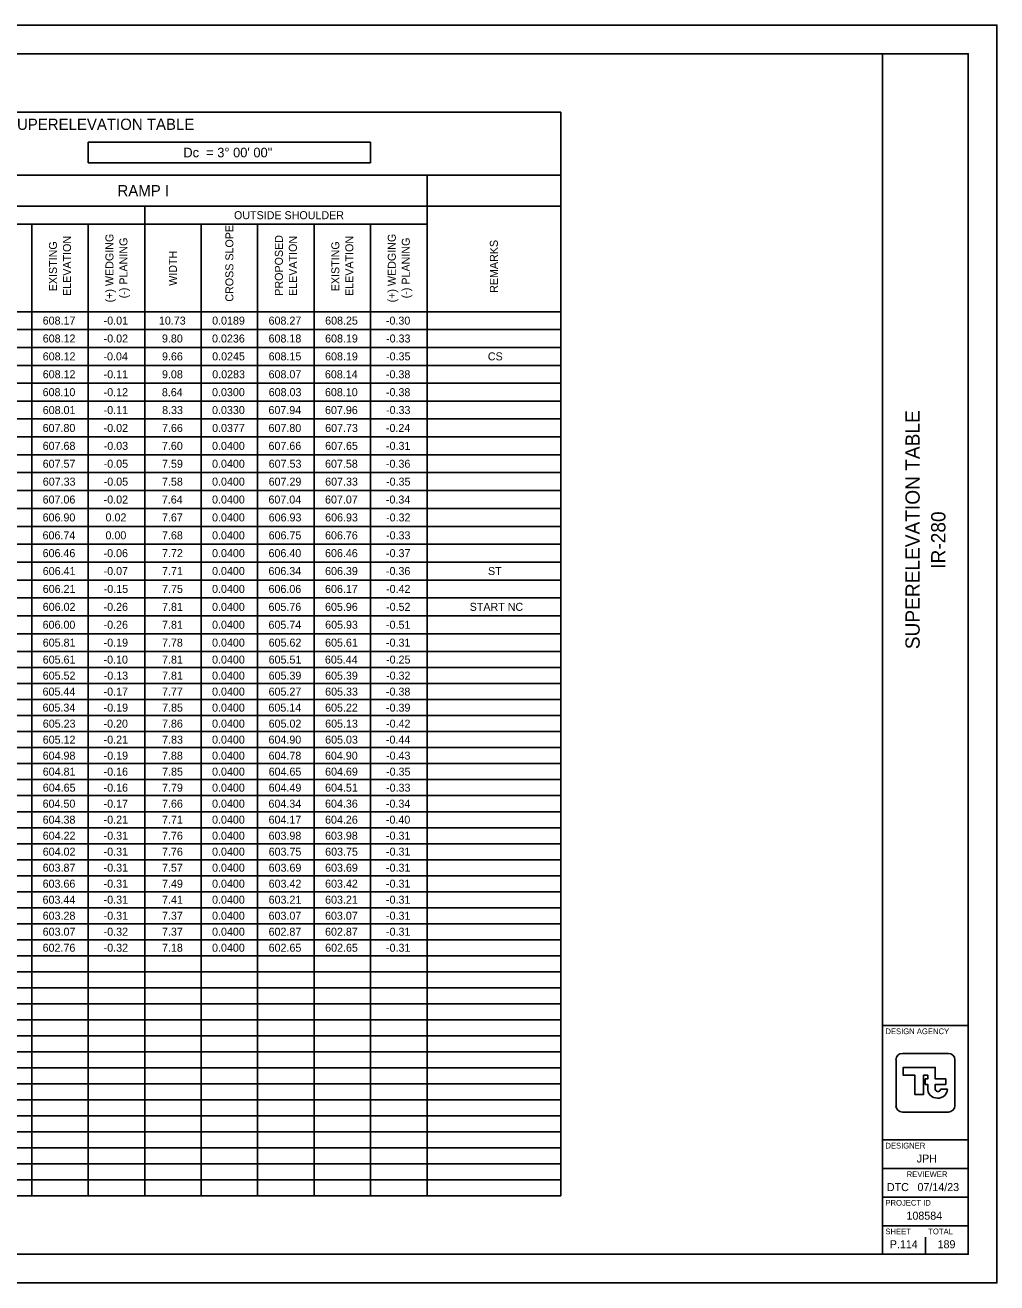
# Model space of a CAD drawing. Extents: x 0 to 34, y 0 to 22.
# Drawn here: x 17 to 34, y 0 to 22 of the extents above; entities that cross this region are included whole.
import ezdxf

# ---------------------------------------------------------------- set-up
doc = ezdxf.new("R2010")
doc.units = 0
for name, color, linetype in [('Default', 7, 'Continuous'), ('SH_Border', 7, 'Continuous'), ('SH_Cut_Line', 7, 'Continuous'), ('SH_Data', 7, 'Continuous')]:
    doc.layers.add(name, color=color, linetype=linetype)

msp = doc.modelspace()

# ---------------------------------------------------------------- linework, layer by layer
at = {"layer": 'Default'}
for p, q in [((7.13, 20.48), (26.368, 20.48)), ((26.368, 20.48), (26.368, 1.522)), ((18.099, 19.953), (23.041, 19.953)), ((18.099, 19.953), (18.099, 19.591)), ((23.041, 19.953), (23.041, 19.591)), ((18.099, 19.591), (23.041, 19.591)), ((7.13, 19.376), (26.368, 19.376)), ((24.029, 19.376), (24.029, 1.522)), ((7.13, 18.833), (26.368, 18.833)), ((19.088, 18.833), (19.088, 1.522)), ((9.205, 18.52), (24.029, 18.52)), ((17.111, 18.52), (17.111, 1.522)), ((18.099, 18.52), (18.099, 1.522)), ((20.076, 18.52), (20.076, 1.522)), ((21.064, 18.52), (21.064, 1.522)), ((22.052, 18.52), (22.052, 1.522)), ((23.041, 18.52), (23.041, 1.522)), ((7.13, 16.988), (26.368, 16.988)), ((7.13, 16.675), (26.368, 16.675)), ((7.13, 16.362), (26.368, 16.362)), ((7.13, 16.049), (26.368, 16.049)), ((7.13, 15.736), (26.368, 15.736)), ((7.13, 15.424), (26.368, 15.424)), ((7.13, 15.111), (26.368, 15.111)), ((7.13, 14.798), (26.368, 14.798)), ((7.13, 14.485), (26.368, 14.485)), ((7.13, 14.172), (26.368, 14.172)), ((7.13, 13.859), (26.368, 13.859)), ((7.13, 13.546), (26.368, 13.546)), ((7.13, 13.233), (26.368, 13.233)), ((7.13, 12.92), (26.368, 12.92)), ((7.13, 12.607), (26.368, 12.607)), ((7.13, 12.294), (26.368, 12.294)), ((7.13, 11.981), (26.368, 11.981)), ((7.13, 11.668), (26.368, 11.668)), ((7.13, 11.355), (26.368, 11.355)), ((7.13, 11.042), (26.368, 11.042)), ((7.13, 10.762), (26.368, 10.762)), ((7.13, 10.482), (26.368, 10.482)), ((7.13, 10.202), (26.368, 10.202)), ((7.13, 9.922), (26.368, 9.922)), ((7.13, 9.642), (26.368, 9.642)), ((7.13, 9.362), (26.368, 9.362)), ((7.13, 9.082), (26.368, 9.082)), ((7.13, 8.802), (26.368, 8.802)), ((7.13, 8.522), (26.368, 8.522)), ((7.13, 8.242), (26.368, 8.242)), ((7.13, 7.962), (26.368, 7.962)), ((7.13, 7.682), (26.368, 7.682)), ((7.13, 7.402), (26.368, 7.402)), ((7.13, 7.122), (26.368, 7.122)), ((7.13, 6.842), (26.368, 6.842)), ((7.13, 6.562), (26.368, 6.562)), ((7.13, 6.282), (26.368, 6.282)), ((7.13, 6.002), (26.368, 6.002)), ((7.13, 5.722), (26.368, 5.722)), ((7.13, 5.442), (26.368, 5.442)), ((7.13, 5.162), (26.368, 5.162)), ((7.13, 4.882), (26.368, 4.882)), ((7.13, 4.602), (26.368, 4.602)), ((7.13, 4.322), (26.368, 4.322)), ((7.13, 4.042), (26.368, 4.042)), ((7.13, 3.762), (26.368, 3.762)), ((7.13, 3.482), (26.368, 3.482)), ((7.13, 3.202), (26.368, 3.202)), ((7.13, 2.922), (26.368, 2.922)), ((7.13, 2.642), (26.368, 2.642)), ((7.13, 2.362), (26.368, 2.362)), ((7.13, 2.082), (26.368, 2.082)), ((7.13, 1.802), (26.368, 1.802)), ((7.13, 1.522), (26.368, 1.522))]:
    msp.add_line(p, q, dxfattribs=at)
at = {"layer": 'SH_Border'}
for p, q in [((32, 0.5), (32, 21.5)), ((32, 4.5), (33.5, 4.5)), ((32, 2.5), (33.5, 2.5)), ((32, 2), (33.5, 2)), ((32, 1.5), (33.5, 1.5)), ((32, 1), (33.5, 1))]:
    msp.add_line(p, q, dxfattribs=at)
msp.add_lwpolyline([(1.5, 21.5), (33.5, 21.5), (33.5, 0.5), (1.5, 0.5)], close=True, dxfattribs=at)
at = {"layer": 'SH_Cut_Line'}
msp.add_lwpolyline([(0, 0), (34, 0), (34, 22), (0, 22)], close=True, dxfattribs=at)
at = {"layer": 'SH_Data'}
for p, q in [((32.75, 3.5), (32.75, 3.5)), ((32.791, 3.415), (32.791, 3.415)), ((33.136, 3.385), (33.015, 3.385)), ((32.375, 0.675), (32.375, 0.675)), ((32.75, 0.5), (32.75, 0.8))]:
    msp.add_line(p, q, dxfattribs=at)
for points in [[(32.348, 4.014), (33.152, 4.014)], [(32.236, 3.099), (32.236, 3.901)], [(32.922, 3.399), (32.922, 3.47), (33.107, 3.47), (33.107, 3.568), (32.922, 3.568), (32.922, 3.768), (32.361, 3.768), (32.361, 3.632), (32.566, 3.632), (32.566, 3.294), (32.715, 3.294), (32.715, 3.63), (32.79, 3.63), (32.79, 3.568), (32.748, 3.568), (32.748, 3.47), (32.79, 3.47), (32.79, 3.415), (32.791, 3.415)], [(33.264, 3.901), (33.264, 3.099)], [(33.152, 2.986), (32.348, 2.986)]]:
    msp.add_lwpolyline(points, dxfattribs=at)
for centre, radius, start, end in [((32.348, 3.901), 0.113, 90, 180), ((33.152, 3.901), 0.113, 360, 90), ((32.949, 3.392), 0.16, 171.8856, 274.8323), ((32.968, 3.392), 0.0473, 171.8856, 350.9243), ((32.976, 3.392), 0.16, 265.1677, 357.3201), ((32.348, 3.099), 0.113, 180, 270), ((33.152, 3.099), 0.113, 270, 360)]:
    msp.add_arc(centre, radius, start, end, dxfattribs=at)

# ---------------------------------------------------------------- texts
at = {"layer": 'Default'}
for s, height, p in [('WOO/LUC-280-06.20/00.00 - SUPERELEVATION TABLE', 0.196, (13.197, 20.168)), ('Dc  = 3° 00\' 00"', 0.168, (19.765, 19.688)), ('RAMP I', 0.196, (18.612, 19.007)), ('OUTSIDE SHOULDER', 0.14, (20.651, 18.606)), ('608.17', 0.14, (17.303, 16.762)), ('-0.01', 0.14, (18.37, 16.762)), ('10.73', 0.14, (19.337, 16.762)), ('0.0189', 0.14, (20.268, 16.762)), ('608.27', 0.14, (21.256, 16.762)), ('608.25', 0.14, (22.246, 16.762)), ('-0.30', 0.14, (23.309, 16.762)), ('608.12', 0.14, (17.304, 16.449)), ('-0.02', 0.14, (18.37, 16.449)), ('9.80', 0.14, (19.39, 16.449)), ('0.0236', 0.14, (20.267, 16.449)), ('608.18', 0.14, (21.256, 16.449)), ('608.19', 0.14, (22.245, 16.449)), ('-0.33', 0.14, (23.312, 16.449)), ('608.12', 0.14, (17.304, 16.136)), ('-0.04', 0.14, (18.367, 16.136)), ('9.66', 0.14, (19.391, 16.136)), ('0.0245', 0.14, (20.269, 16.136)), ('608.15', 0.14, (21.257, 16.136)), ('608.19', 0.14, (22.245, 16.136)), ('-0.35', 0.14, (23.312, 16.136)), ('CS', 0.14, (25.093, 16.136)), ('608.12', 0.14, (17.304, 15.823)), ('-0.11', 0.14, (18.37, 15.823)), ('9.08', 0.14, (19.391, 15.823)), ('0.0283', 0.14, (20.27, 15.823)), ('608.07', 0.14, (21.256, 15.823)), ('608.14', 0.14, (22.242, 15.823)), ('-0.38', 0.14, (23.31, 15.823)), ('608.10', 0.14, (17.302, 15.51)), ('-0.12', 0.14, (18.37, 15.51)), ('8.64', 0.14, (19.389, 15.51)), ('0.0300', 0.14, (20.267, 15.51)), ('608.03', 0.14, (21.258, 15.51)), ('608.10', 0.14, (22.243, 15.51)), ('-0.38', 0.14, (23.31, 15.51)), ('608.01', 0.14, (17.304, 15.197)), ('-0.11', 0.14, (18.37, 15.197)), ('8.33', 0.14, (19.393, 15.197)), ('0.0330', 0.14, (20.267, 15.197)), ('607.94', 0.14, (21.254, 15.197)), ('607.96', 0.14, (22.244, 15.197)), ('-0.33', 0.14, (23.312, 15.197)), ('607.80', 0.14, (17.302, 14.884)), ('-0.02', 0.14, (18.37, 14.884)), ('7.66', 0.14, (19.391, 14.884)), ('0.0377', 0.14, (20.268, 14.884)), ('607.80', 0.14, (21.255, 14.884)), ('607.73', 0.14, (22.246, 14.884)), ('-0.24', 0.14, (23.309, 14.884)), ('607.68', 0.14, (17.303, 14.571)), ('-0.03', 0.14, (18.371, 14.571)), ('7.60', 0.14, (19.39, 14.571)), ('0.0400', 0.14, (20.267, 14.571)), ('607.66', 0.14, (21.255, 14.571)), ('607.65', 0.14, (22.246, 14.571)), ('-0.31', 0.14, (23.311, 14.571)), ('607.57', 0.14, (17.303, 14.258)), ('-0.05', 0.14, (18.371, 14.258)), ('7.59', 0.14, (19.392, 14.258)), ('0.0400', 0.14, (20.267, 14.258)), ('607.53', 0.14, (21.258, 14.258)), ('607.58', 0.14, (22.244, 14.258)), ('-0.36', 0.14, (23.31, 14.258)), ('607.33', 0.14, (17.305, 13.945)), ('-0.05', 0.14, (18.371, 13.945)), ('7.58', 0.14, (19.391, 13.945)), ('0.0400', 0.14, (20.267, 13.945)), ('607.29', 0.14, (21.257, 13.945)), ('607.33', 0.14, (22.246, 13.945)), ('-0.35', 0.14, (23.312, 13.945)), ('607.06', 0.14, (17.302, 13.632)), ('-0.02', 0.14, (18.37, 13.632)), ('7.64', 0.14, (19.389, 13.632)), ('0.0400', 0.14, (20.267, 13.632)), ('607.04', 0.14, (21.254, 13.632)), ('607.07', 0.14, (22.244, 13.632)), ('-0.34', 0.14, (23.309, 13.632)), ('606.90', 0.14, (17.302, 13.319)), ('0.02', 0.14, (18.404, 13.319)), ('7.67', 0.14, (19.391, 13.319)), ('0.0400', 0.14, (20.267, 13.319)), ('606.93', 0.14, (21.258, 13.319)), ('606.93', 0.14, (22.246, 13.319)), ('-0.32', 0.14, (23.312, 13.319)), ('606.74', 0.14, (17.301, 13.006)), ('0.00', 0.14, (18.402, 13.006)), ('7.68', 0.14, (19.391, 13.006)), ('0.0400', 0.14, (20.267, 13.006)), ('606.75', 0.14, (21.257, 13.006)), ('606.76', 0.14, (22.244, 13.006)), ('-0.33', 0.14, (23.312, 13.006)), ('606.46', 0.14, (17.302, 12.694)), ('-0.06', 0.14, (18.369, 12.694)), ('7.72', 0.14, (19.392, 12.694)), ('0.0400', 0.14, (20.267, 12.694)), ('606.40', 0.14, (21.255, 12.694)), ('606.46', 0.14, (22.244, 12.694)), ('-0.37', 0.14, (23.311, 12.694)), ('606.41', 0.14, (17.304, 12.381)), ('-0.07', 0.14, (18.369, 12.381)), ('7.71', 0.14, (19.392, 12.381)), ('0.0400', 0.14, (20.267, 12.381)), ('606.34', 0.14, (21.254, 12.381)), ('606.39', 0.14, (22.245, 12.381)), ('-0.36', 0.14, (23.31, 12.381)), ('ST', 0.14, (25.095, 12.381)), ('606.21', 0.14, (17.304, 12.068)), ('-0.15', 0.14, (18.371, 12.068)), ('7.75', 0.14, (19.393, 12.068)), ('0.0400', 0.14, (20.267, 12.068)), ('606.06', 0.14, (21.255, 12.068)), ('606.17', 0.14, (22.244, 12.068)), ('-0.42', 0.14, (23.312, 12.068)), ('606.02', 0.14, (17.304, 11.755)), ('-0.26', 0.14, (18.369, 11.755)), ('7.81', 0.14, (19.392, 11.755)), ('0.0400', 0.14, (20.267, 11.755)), ('605.76', 0.14, (21.255, 11.755)), ('605.96', 0.14, (22.244, 11.755)), ('-0.52', 0.14, (23.312, 11.755)), ('START NC', 0.14, (24.775, 11.755)), ('606.00', 0.14, (17.302, 11.442)), ('-0.26', 0.14, (18.369, 11.442)), ('7.81', 0.14, (19.392, 11.442)), ('0.0400', 0.14, (20.267, 11.442)), ('605.74', 0.14, (21.254, 11.442)), ('605.93', 0.14, (22.246, 11.442)), ('-0.51', 0.14, (23.311, 11.442)), ('605.81', 0.14, (17.304, 11.129)), ('-0.19', 0.14, (18.37, 11.129)), ('7.78', 0.14, (19.391, 11.129)), ('0.0400', 0.14, (20.267, 11.129)), ('605.62', 0.14, (21.257, 11.129)), ('605.61', 0.14, (22.245, 11.129)), ('-0.31', 0.14, (23.311, 11.129)), ('605.61', 0.14, (17.304, 10.832)), ('-0.10', 0.14, (18.368, 10.832)), ('7.81', 0.14, (19.392, 10.832)), ('0.0400', 0.14, (20.267, 10.832)), ('605.51', 0.14, (21.257, 10.832)), ('605.44', 0.14, (22.242, 10.832)), ('-0.25', 0.14, (23.312, 10.832)), ('605.52', 0.14, (17.304, 10.552)), ('-0.13', 0.14, (18.371, 10.552)), ('7.81', 0.14, (19.392, 10.552)), ('0.0400', 0.14, (20.267, 10.552)), ('605.39', 0.14, (21.257, 10.552)), ('605.39', 0.14, (22.245, 10.552)), ('-0.32', 0.14, (23.312, 10.552)), ('605.44', 0.14, (17.301, 10.272)), ('-0.17', 0.14, (18.369, 10.272)), ('7.77', 0.14, (19.391, 10.272)), ('0.0400', 0.14, (20.267, 10.272)), ('605.27', 0.14, (21.256, 10.272)), ('605.33', 0.14, (22.246, 10.272)), ('-0.38', 0.14, (23.31, 10.272)), ('605.34', 0.14, (17.301, 9.992)), ('-0.19', 0.14, (18.37, 9.992)), ('7.85', 0.14, (19.393, 9.992)), ('0.0400', 0.14, (20.267, 9.992)), ('605.14', 0.14, (21.254, 9.992)), ('605.22', 0.14, (22.245, 9.992)), ('-0.39', 0.14, (23.311, 9.992)), ('605.23', 0.14, (17.305, 9.712)), ('-0.20', 0.14, (18.368, 9.712)), ('7.86', 0.14, (19.391, 9.712)), ('0.0400', 0.14, (20.267, 9.712)), ('605.02', 0.14, (21.257, 9.712)), ('605.13', 0.14, (22.246, 9.712)), ('-0.42', 0.14, (23.312, 9.712)), ('605.12', 0.14, (17.304, 9.432)), ('-0.21', 0.14, (18.37, 9.432)), ('7.83', 0.14, (19.393, 9.432)), ('0.0400', 0.14, (20.267, 9.432)), ('604.90', 0.14, (21.255, 9.432)), ('605.03', 0.14, (22.246, 9.432)), ('-0.44', 0.14, (23.309, 9.432)), ('604.98', 0.14, (17.303, 9.152)), ('-0.19', 0.14, (18.37, 9.152)), ('7.88', 0.14, (19.391, 9.152)), ('0.0400', 0.14, (20.267, 9.152)), ('604.78', 0.14, (21.256, 9.152)), ('604.90', 0.14, (22.243, 9.152)), ('-0.43', 0.14, (23.312, 9.152)), ('604.81', 0.14, (17.304, 8.872)), ('-0.16', 0.14, (18.369, 8.872)), ('7.85', 0.14, (19.393, 8.872)), ('0.0400', 0.14, (20.267, 8.872)), ('604.65', 0.14, (21.257, 8.872)), ('604.69', 0.14, (22.245, 8.872)), ('-0.35', 0.14, (23.312, 8.872)), ('604.65', 0.14, (17.305, 8.592)), ('-0.16', 0.14, (18.369, 8.592)), ('7.79', 0.14, (19.392, 8.592)), ('0.0400', 0.14, (20.267, 8.592)), ('604.49', 0.14, (21.257, 8.592)), ('604.51', 0.14, (22.245, 8.592)), ('-0.33', 0.14, (23.312, 8.592)), ('604.50', 0.14, (17.302, 8.312)), ('-0.17', 0.14, (18.369, 8.312)), ('7.66', 0.14, (19.391, 8.312)), ('0.0400', 0.14, (20.267, 8.312)), ('604.34', 0.14, (21.254, 8.312)), ('604.36', 0.14, (22.244, 8.312)), ('-0.34', 0.14, (23.309, 8.312)), ('604.38', 0.14, (17.303, 8.032)), ('-0.21', 0.14, (18.37, 8.032)), ('7.71', 0.14, (19.392, 8.032)), ('0.0400', 0.14, (20.267, 8.032)), ('604.17', 0.14, (21.256, 8.032)), ('604.26', 0.14, (22.244, 8.032)), ('-0.40', 0.14, (23.309, 8.032)), ('604.22', 0.14, (17.304, 7.752)), ('-0.31', 0.14, (18.37, 7.752)), ('7.76', 0.14, (19.391, 7.752)), ('0.0400', 0.14, (20.267, 7.752)), ('603.98', 0.14, (21.256, 7.752)), ('603.98', 0.14, (22.244, 7.752)), ('-0.31', 0.14, (23.311, 7.752)), ('604.02', 0.14, (17.304, 7.472)), ('-0.31', 0.14, (18.37, 7.472)), ('7.76', 0.14, (19.391, 7.472)), ('0.0400', 0.14, (20.267, 7.472)), ('603.75', 0.14, (21.257, 7.472)), ('603.75', 0.14, (22.246, 7.472)), ('-0.31', 0.14, (23.311, 7.472)), ('603.87', 0.14, (17.303, 7.192)), ('-0.31', 0.14, (18.37, 7.192)), ('7.57', 0.14, (19.391, 7.192)), ('0.0400', 0.14, (20.267, 7.192)), ('603.69', 0.14, (21.257, 7.192)), ('603.69', 0.14, (22.245, 7.192)), ('-0.31', 0.14, (23.311, 7.192)), ('603.66', 0.14, (17.302, 6.912)), ('-0.31', 0.14, (18.37, 6.912)), ('7.49', 0.14, (19.392, 6.912)), ('0.0400', 0.14, (20.267, 6.912)), ('603.42', 0.14, (21.257, 6.912)), ('603.42', 0.14, (22.245, 6.912)), ('-0.31', 0.14, (23.311, 6.912)), ('603.44', 0.14, (17.301, 6.632)), ('-0.31', 0.14, (18.37, 6.632)), ('7.41', 0.14, (19.392, 6.632)), ('0.0400', 0.14, (20.267, 6.632)), ('603.21', 0.14, (21.257, 6.632)), ('603.21', 0.14, (22.245, 6.632)), ('-0.31', 0.14, (23.311, 6.632)), ('603.28', 0.14, (17.303, 6.352)), ('-0.31', 0.14, (18.37, 6.352)), ('7.37', 0.14, (19.391, 6.352)), ('0.0400', 0.14, (20.267, 6.352)), ('603.07', 0.14, (21.256, 6.352)), ('603.07', 0.14, (22.244, 6.352)), ('-0.31', 0.14, (23.311, 6.352)), ('603.07', 0.14, (17.303, 6.072)), ('-0.32', 0.14, (18.37, 6.072)), ('7.37', 0.14, (19.391, 6.072)), ('0.0400', 0.14, (20.267, 6.072)), ('602.87', 0.14, (21.256, 6.072)), ('602.87', 0.14, (22.244, 6.072)), ('-0.31', 0.14, (23.311, 6.072)), ('602.76', 0.14, (17.302, 5.792)), ('-0.32', 0.14, (18.37, 5.792)), ('7.18', 0.14, (19.391, 5.792)), ('0.0400', 0.14, (20.267, 5.792)), ('602.65', 0.14, (21.257, 5.792)), ('602.65', 0.14, (22.246, 5.792)), ('-0.31', 0.14, (23.311, 5.792))]:
    msp.add_text(s, height=height, dxfattribs=at).set_placement(p)
for s, p in [('CROSS SLOPE', (20.64, 17.163)), ('ELEVATION', (17.798, 17.263)), ('(+) WEDGING', (18.541, 17.15)), ('(-) PLANING', (18.786, 17.222)), ('PROPOSED ', (21.506, 17.267)), ('ELEVATION', (21.751, 17.263)), ('ELEVATION', (22.739, 17.263)), ('(+) WEDGING', (23.482, 17.15)), ('(-) PLANING', (23.727, 17.222)), ('EXISTING ', (17.553, 17.345)), ('EXISTING ', (22.494, 17.345)), ('REMARKS', (25.268, 17.317)), ('WIDTH', (19.652, 17.441))]:
    msp.add_text(s, height=0.14, rotation=90, dxfattribs=at).set_placement(p)
at = {"layer": 'SH_Data'}
for s, p in [('SUPERELEVATION TABLE', (32.65, 11.084)), ('IR-280', (33.1, 12.491))]:
    msp.add_text(s, height=0.25, rotation=90, dxfattribs=at).set_placement(p)
for s, height, p in [('DESIGN AGENCY', 0.1, (32.05, 4.35)), ('DESIGNER', 0.1, (32.05, 2.35)), ('JPH', 0.14, (32.598, 2.105)), ('REVIEWER', 0.1, (32.422, 1.85)), ('DTC', 0.14, (32.076, 1.605)), ('07/14/23', 0.14, (32.611, 1.605)), ('PROJECT ID', 0.1, (32.05, 1.35)), ('108584', 0.14, (32.418, 1.105)), ('SHEET', 0.1, (32.05, 0.85)), ('TOTAL', 0.1, (32.8, 0.85)), ('P.114', 0.14, (32.126, 0.605)), ('189', 0.14, (32.963, 0.605))]:
    msp.add_text(s, height=height, dxfattribs=at).set_placement(p)

doc.saveas('drawing.dxf')
